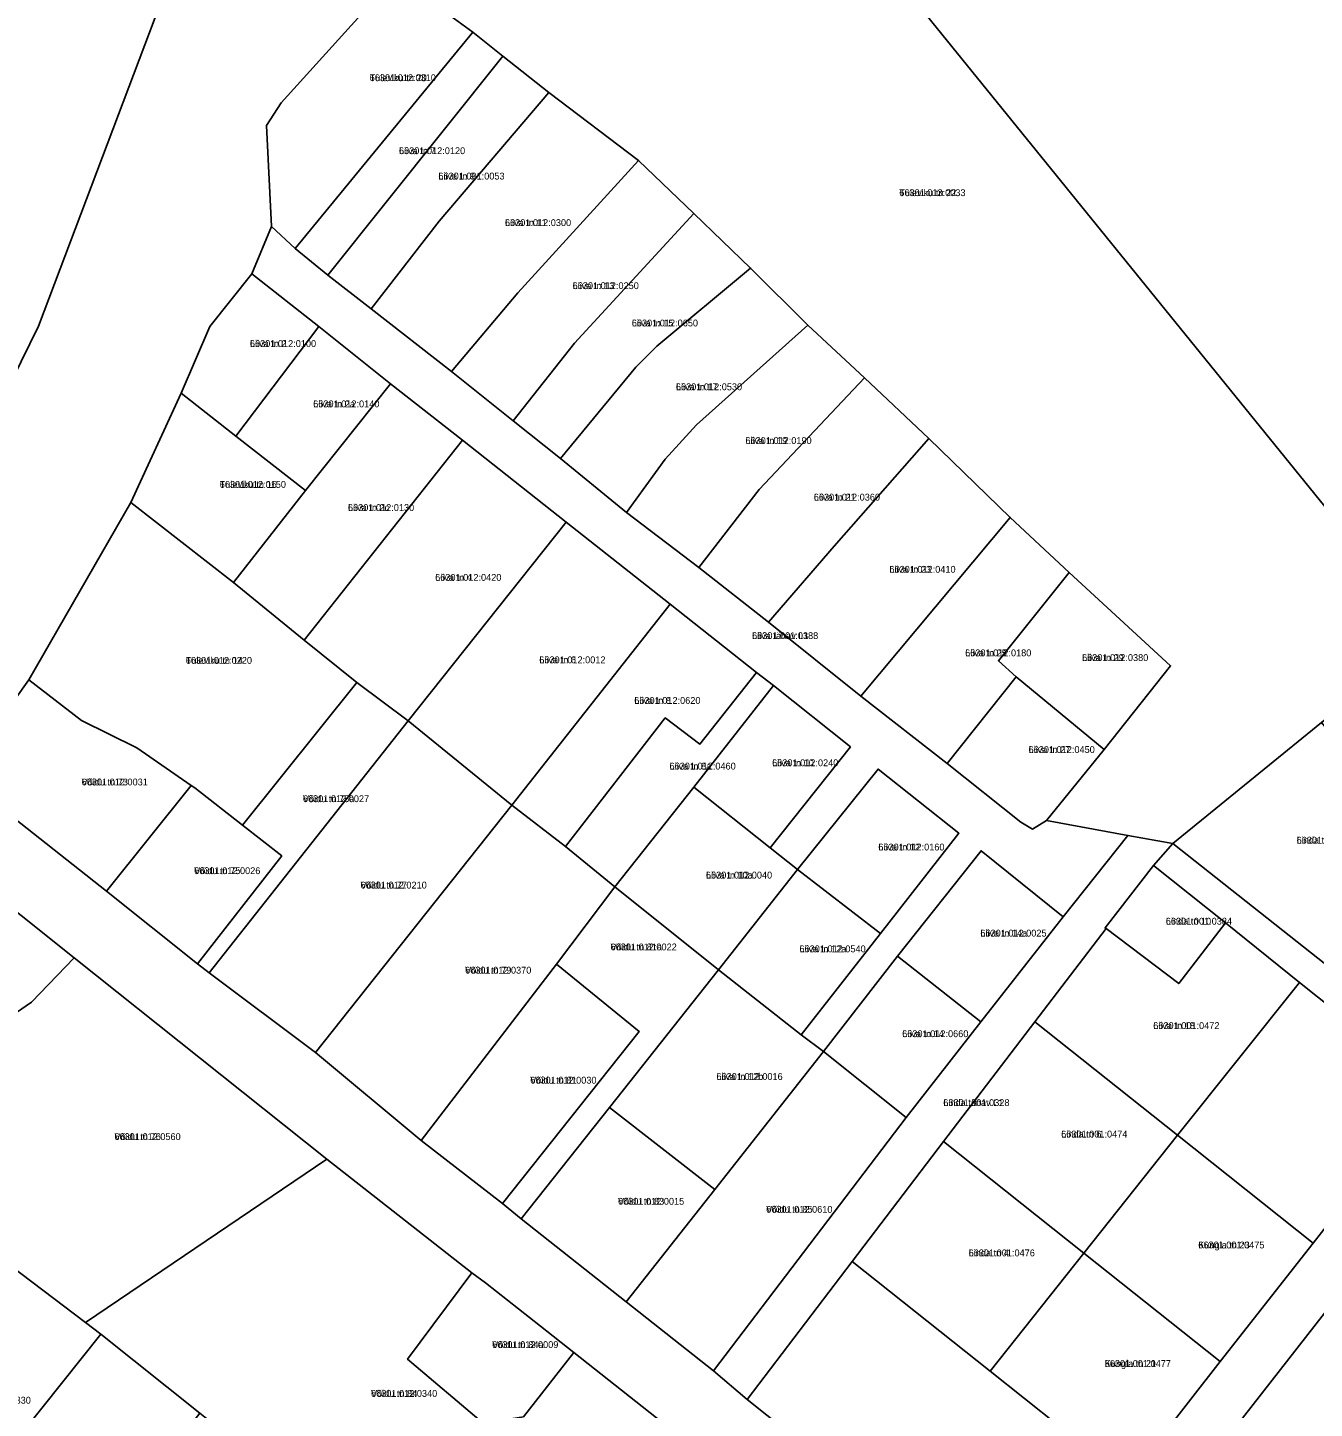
# Model space of a CAD drawing. Extents: x 632278 to 636344, y 6578401 to 6583362.
# Drawn here: x 634837.7 to 635119.5, y 6580958 to 6581260.6 of the extents above; entities that cross this region are included whole.
import ezdxf

# ---------------------------------------------------------------- set-up
doc = ezdxf.new("R2010")
doc.units = 0
for name, color, linetype in [('L_AADRESS', 7, 'Continuous'), ('PIIR', 7, 'Continuous'), ('TUNNUS', 7, 'Continuous')]:
    doc.layers.add(name, color=color, linetype=linetype)

msp = doc.modelspace()

# ---------------------------------------------------------------- linework, layer by layer
at = {"layer": 'PIIR'}
for points in [[(634912.6, 6581276.11), (634946.53, 6581362.44), (634969.39, 6581343.75), (635144.63, 6581127.44), (635121.09, 6581108.27), (635088.56, 6581081.79), (635078.7, 6581083.55), (635060.83, 6581086.86), (635073.49, 6581102.38), (635088.03, 6581120.73), (635065.85, 6581141.16), (635052.91, 6581153.23), (635035.09, 6581170.5), (635020.97, 6581183.85), (635008.56, 6581195.34), (634996.04, 6581207.85), (634983.63, 6581219.79), (634971.52, 6581231.46), (634951.87, 6581246.32), (634941.81, 6581254.33), (634935.24, 6581259.55), (634918.34, 6581271.91)], [(634891.17, 6581216.96), (634890.04, 6581239.13), (634893.28, 6581244.04), (634918.34, 6581271.91), (634935.24, 6581259.55), (634896.29, 6581212.18)], [(634941.81, 6581254.33), (634903.49, 6581206.31), (634896.29, 6581212.18), (634935.24, 6581259.55)], [(634913, 6581198.95), (634903.49, 6581206.31), (634941.81, 6581254.33), (634951.87, 6581246.32), (634927.84, 6581218.12)], [(634913, 6581198.95), (634927.84, 6581218.12), (634951.87, 6581246.32), (634971.52, 6581231.46), (634945.1, 6581202.46), (634930.53, 6581185.23)], [(634930.53, 6581185.23), (634945.1, 6581202.46), (634971.52, 6581231.46), (634983.63, 6581219.79), (634957.47, 6581191.41), (634944.03, 6581174.38)], [(634954.42, 6581166.12), (634944.03, 6581174.38), (634957.47, 6581191.41), (634983.63, 6581219.79), (634996.04, 6581207.85), (634975.49, 6581190.74), (634970.9, 6581186.18)], [(634891.17, 6581216.96), (634896.29, 6581212.18), (634903.49, 6581206.31), (634913, 6581198.95), (634930.53, 6581185.23), (634944.03, 6581174.38), (634954.42, 6581166.12), (634968.89, 6581154.34), (634984.7, 6581142.28), (634999.99, 6581130.26), (635020.23, 6581114.1), (635039.14, 6581099.3), (635055.25, 6581086.43), (635057.76, 6581084.93), (635060.83, 6581086.86), (635078.7, 6581083.55), (635064.51, 6581065.71), (635046.54, 6581080.19), (635028.23, 6581057.07), (635011.99, 6581036.2), (635007.12, 6581039.87), (635024.49, 6581062.1), (635041.69, 6581084.03), (635023.98, 6581098.09), (635006.34, 6581076.09), (635000.36, 6581080.85), (635017.9, 6581102.94), (635001.07, 6581116.44), (634997.38, 6581119.29), (634978.46, 6581134.22), (634955.69, 6581152.16), (634932.94, 6581170.18), (634917.19, 6581182.5), (634901.48, 6581195.03), (634886.85, 6581206.58)], [(634901.48, 6581195.03), (634883.34, 6581171.06), (634871.35, 6581180.44), (634877.61, 6581195.05), (634886.85, 6581206.58)], [(634968.89, 6581154.34), (634954.42, 6581166.12), (634970.9, 6581186.18), (634975.49, 6581190.74), (634996.04, 6581207.85), (635008.56, 6581195.34), (634984.22, 6581173.52), (634977.38, 6581166.03)], [(634883.34, 6581171.06), (634901.48, 6581195.03), (634917.19, 6581182.5), (634898.55, 6581159.15)], [(634968.89, 6581154.34), (634977.38, 6581166.03), (634984.22, 6581173.52), (635008.56, 6581195.34), (635020.97, 6581183.85), (634997.91, 6581159.38), (634984.7, 6581142.28)], [(634898.28, 6581126.31), (634882.81, 6581138.99), (634898.55, 6581159.15), (634917.19, 6581182.5), (634932.94, 6581170.18)], [(634984.7, 6581142.28), (634997.91, 6581159.38), (635020.97, 6581183.85), (635035.09, 6581170.5), (635014.36, 6581146.92), (634999.99, 6581130.26)], [(634871.35, 6581180.44), (634883.34, 6581171.06), (634898.55, 6581159.15), (634882.81, 6581138.99), (634860.3, 6581156.51)], [(634909.84, 6581117.05), (634898.28, 6581126.31), (634932.94, 6581170.18), (634955.69, 6581152.16), (634921.1, 6581108.63)], [(634999.99, 6581130.26), (635014.36, 6581146.92), (635035.09, 6581170.5), (635052.91, 6581153.23), (635020.23, 6581114.1)], [(634860.3, 6581156.51), (634882.81, 6581138.99), (634898.28, 6581126.31), (634909.84, 6581117.05), (634884.81, 6581085.8), (634874.38, 6581094.02), (634873.56, 6581094.5), (634861.66, 6581102.77), (634849.52, 6581108.77), (634838.01, 6581117.66)], [(634921.1, 6581108.63), (634955.69, 6581152.16), (634978.46, 6581134.22), (634943.78, 6581090.22)], [(635020.23, 6581114.1), (635052.91, 6581153.23), (635065.85, 6581141.16), (635050.33, 6581121.83), (635054.24, 6581118.31), (635039.14, 6581099.3)], [(635050.33, 6581121.83), (635065.85, 6581141.16), (635088.03, 6581120.73), (635073.49, 6581102.38), (635054.24, 6581118.31)], [(634955.53, 6581081.13), (634943.78, 6581090.22), (634978.46, 6581134.22), (634997.38, 6581119.29), (634984.95, 6581103.56), (634977.36, 6581109.29)], [(634955.53, 6581081.13), (634977.36, 6581109.29), (634984.95, 6581103.56), (634997.38, 6581119.29), (635001.07, 6581116.44), (634983.65, 6581094.15), (634966.3, 6581072.26)], [(634838.01, 6581117.66), (634849.52, 6581108.77), (634861.66, 6581102.77), (634873.56, 6581094.5), (634855, 6581071.36), (634822.93, 6581096.59)], [(634909.84, 6581117.05), (634921.1, 6581108.63), (634877.49, 6581053.44), (634874.93, 6581055.45), (634893.4, 6581079.06), (634884.81, 6581085.8)], [(634983.65, 6581094.15), (635001.07, 6581116.44), (635017.9, 6581102.94), (635000.36, 6581080.85)], [(635039.14, 6581099.3), (635054.24, 6581118.31), (635073.49, 6581102.38), (635060.83, 6581086.86), (635057.76, 6581084.93), (635055.25, 6581086.43)], [(634877.49, 6581053.44), (634921.1, 6581108.63), (634943.78, 6581090.22), (634900.78, 6581036.03)], [(635088.56, 6581081.79), (635121.09, 6581108.27), (635147.43, 6581075.93), (635122.03, 6581055.25)], [(635023.98, 6581098.09), (635041.69, 6581084.03), (635024.49, 6581062.1), (635006.34, 6581076.09)], [(634873.56, 6581094.5), (634874.38, 6581094.02), (634884.81, 6581085.8), (634893.4, 6581079.06), (634874.93, 6581055.45), (634855, 6581071.36)], [(634989.03, 6581054.08), (634966.3, 6581072.26), (634983.65, 6581094.15), (635000.36, 6581080.85), (635006.34, 6581076.09)], [(634900.78, 6581036.03), (634943.78, 6581090.22), (634955.53, 6581081.13), (634966.3, 6581072.26), (634953.54, 6581055.33), (634923.95, 6581016.73)], [(634797.56, 6581064.7), (634813.01, 6581084.53), (634847.95, 6581056.76), (634838.59, 6581047), (634823.5, 6581036.63), (634816.61, 6581047.12)], [(635018.27, 6580990.22), (634995.29, 6580959.95), (634987.94, 6580966.28), (635030.15, 6581021.74), (635046.51, 6581042.71), (635064.51, 6581065.71), (635078.7, 6581083.55), (635088.56, 6581081.79), (635084.3, 6581076.94), (635073.69, 6581063.3), (635073.91, 6581063.14), (635058.32, 6581042.73), (635038.31, 6581016.48)], [(635046.54, 6581080.19), (635064.51, 6581065.71), (635046.51, 6581042.71), (635028.23, 6581057.07)], [(635084.3, 6581076.94), (635088.56, 6581081.79), (635122.03, 6581055.25), (635156.7, 6581027.77), (635150.67, 6581023.97), (635116.28, 6581051.35), (635100.04, 6581064.4)], [(634989.03, 6581054.08), (635006.34, 6581076.09), (635024.49, 6581062.1), (635007.12, 6581039.87)], [(635073.69, 6581063.3), (635084.3, 6581076.94), (635100.04, 6581064.4), (635089.81, 6581051.08), (635073.91, 6581063.14)], [(634966.3, 6581072.26), (634989.03, 6581054.08), (634965.17, 6581023.94), (634945.82, 6580999.55), (634941.76, 6581002.89), (634971.67, 6581040.58), (634953.54, 6581055.32)], [(635058.32, 6581042.73), (635073.91, 6581063.14), (635089.81, 6581051.08), (635100.04, 6581064.4), (635116.28, 6581051.35), (635089.57, 6581017.88)], [(634831.74, 6580991), (634809.41, 6581009.48), (634816.8, 6581018.45), (634823.5, 6581036.63), (634838.59, 6581047), (634847.95, 6581056.76), (634903.28, 6581012.64), (634850.41, 6580976.85)], [(634971.67, 6581040.58), (634941.76, 6581002.89), (634923.95, 6581016.73), (634953.54, 6581055.33)], [(635028.23, 6581057.07), (635046.51, 6581042.71), (635030.15, 6581021.74), (635011.99, 6581036.2)], [(635055.23, 6580912.22), (635078.63, 6580942.2), (635098.91, 6580968.26), (635119.24, 6580994.25), (635124.71, 6581001.23), (635141.35, 6581018.03), (635150.67, 6581023.97), (635156.7, 6581027.77), (635176.39, 6581040.35), (635202.1, 6581056.83), (635209.39, 6581047.9), (635185.68, 6581032.75), (635160.13, 6581016.49), (635148.57, 6581009.1), (635133.75, 6580994.18), (635127.71, 6580986.57), (635064.19, 6580905.18)], [(634989.03, 6581054.08), (635007.12, 6581039.87), (635011.99, 6581036.2), (634988.21, 6581005.98), (634965.17, 6581023.94)], [(635089.57, 6581017.88), (635116.28, 6581051.35), (635150.67, 6581023.97), (635141.35, 6581018.03), (635124.71, 6581001.23), (635119.24, 6580994.25)], [(635038.31, 6581016.48), (635058.32, 6581042.73), (635089.57, 6581017.88), (635069.02, 6580992)], [(634968.82, 6580981.35), (634988.21, 6581005.98), (635011.99, 6581036.2), (635030.15, 6581021.74), (634987.94, 6580966.28)], [(634965.17, 6581023.94), (634988.21, 6581005.98), (634968.82, 6580981.35), (634945.82, 6580999.55)], [(635018.27, 6580990.22), (635038.31, 6581016.48), (635069.02, 6580992), (635048.49, 6580966.2)], [(635069.02, 6580992), (635089.57, 6581017.88), (635119.24, 6580994.25), (635098.91, 6580968.26)], [(634875.44, 6580957), (634853.77, 6580974.29), (634850.41, 6580976.85), (634903.28, 6581012.64), (634934.98, 6580987.7), (634920.94, 6580968.79), (634937.47, 6580954.77), (634946.29, 6580956.14), (634957.35, 6580970.29), (634975.46, 6580955.95), (634950.81, 6580940.29), (634911.03, 6580914.84), (634907.81, 6580920.62), (634897.33, 6580939.45)], [(635048.49, 6580966.2), (635069.02, 6580992), (635098.91, 6580968.26), (635078.63, 6580942.2)], [(634831.74, 6580991), (634850.41, 6580976.85), (634853.77, 6580974.29), (634815.84, 6580926.73), (634794.1, 6580943.95)], [(634995.29, 6580959.95), (635018.27, 6580990.22), (635048.49, 6580966.2), (635078.63, 6580942.2), (635055.23, 6580912.22)], [(634934.98, 6580987.7), (634937.98, 6580985.51), (634950.06, 6580976.06), (634957.35, 6580970.29), (634946.29, 6580956.14), (634937.47, 6580954.77), (634920.94, 6580968.79)], [(635127.71, 6580986.57), (635212.9, 6580920.1), (635148.77, 6580837.91), (635064.19, 6580905.18)], [(634815.84, 6580926.73), (634853.77, 6580974.29), (634875.44, 6580957), (634862.3, 6580940.1), (634850.08, 6580924.68), (634837.9, 6580909.32)]]:
    msp.add_lwpolyline(points, close=True, dxfattribs=at)
for points in [[(634918.34, 6581271.91), (634893.28, 6581244.04), (634890.04, 6581239.13), (634891.17, 6581216.96), (634886.85, 6581206.58), (634877.61, 6581195.05), (634871.35, 6581180.44), (634860.3, 6581156.51), (634838.01, 6581117.66), (634822.93, 6581096.59), (634813.01, 6581084.53), (634783.31, 6581109.93), (634796.07, 6581117.73), (634809.38, 6581135.31), (634822.93, 6581160.31), (634840.08, 6581195.15), (634865.69, 6581262.77)], [(634865.69, 6581262.77), (634840.08, 6581195.15), (634822.93, 6581160.31), (634809.38, 6581135.31), (634796.07, 6581117.73), (634764.96, 6581143.81), (634714.31, 6581221.64), (634742.28, 6581238.5), (634753.1, 6581245.04), (634757.02, 6581255.3), (634760.32, 6581263.95)], [(634822.93, 6581096.59), (634855, 6581071.36), (634874.93, 6581055.45), (634877.49, 6581053.44), (634900.78, 6581036.03), (634923.95, 6581016.73), (634941.76, 6581002.89), (634945.82, 6580999.55), (634968.82, 6580981.35), (634987.94, 6580966.28), (634995.29, 6580959.95), (635055.23, 6580912.22), (635064.19, 6580905.18), (635148.77, 6580837.91), (635156.38, 6580831.87), (635270.51, 6580741.99)], [(635262.41, 6580731.79), (635191.38, 6580787.53), (635172.4, 6580802.21), (635167.86, 6580805.69), (635151.82, 6580817.9), (635132.3, 6580833.01), (635112.35, 6580848.22), (635094.77, 6580862.04), (635091.62, 6580864.51), (635054.05, 6580893.93), (635045.98, 6580900.27), (635022.45, 6580918.7), (634997.82, 6580937.94), (634977.82, 6580954.21), (634975.46, 6580955.95), (634957.35, 6580970.29), (634950.06, 6580976.06), (634937.98, 6580985.51), (634934.98, 6580987.7), (634903.28, 6581012.64), (634847.95, 6581056.76), (634813.01, 6581084.53)]]:
    msp.add_lwpolyline(points, dxfattribs=at)

# ---------------------------------------------------------------- texts
at = {"layer": 'L_AADRESS'}
for s, p in [('Tuleviku tn 20', (634912.64, 6581248.82)), ('Liiva tn 7', (634919.05, 6581232.83)), ('Liiva tn 9', (634927.68, 6581227.27)), ('Tuleviku tn 22', (635028.62, 6581223.63)), ('Liiva tn 11', (634942.26, 6581217.07)), ('Liiva tn 13', (634957.08, 6581203.26)), ('Liiva tn 15', (634970.04, 6581195.08)), ('Liiva tn 2', (634886.41, 6581190.58)), ('Liiva tn 17', (634979.7, 6581181.1)), ('Liiva tn 2a', (634900.27, 6581177.36)), ('Liiva tn 19', (634994.93, 6581169.32)), ('Tuleviku tn 16', (634879.8, 6581159.71)), ('Liiva tn 21', (635009.9, 6581156.92)), ('Liiva tn 2c', (634907.88, 6581154.64)), ('Liiva tn 23', (635026.45, 6581141.11)), ('Liiva tn 4', (634926.98, 6581139.34)), ('Liiva tänav L1', (634996.37, 6581126.58)), ('Tuleviku tn 14', (634872.37, 6581121.16)), ('Liiva tn 6', (634949.78, 6581121.28)), ('Liiva tn 25', (635043.04, 6581122.81)), ('Liiva tn 29', (635068.65, 6581121.77)), ('Liiva tn 8', (634970.58, 6581112.38)), ('Liiva tn 10', (635000.77, 6581098.72)), ('Liiva tn 27', (635056.93, 6581101.62)), ('Liiva tn 8a', (634978.3, 6581097.99)), ('Võidu tn 73', (634849.56, 6581094.51)), ('Võidu tn 75a', (634898.02, 6581090.85)), ('Linda tn 12', (635115.64, 6581081.76)), ('Liiva tn 12', (635024.02, 6581080.26)), ('Võidu tn 75', (634874.2, 6581075.08)), ('Võidu tn 77', (634910.64, 6581071.92)), ('Liiva tn 10a', (634986.28, 6581074.11)), ('Linda tn 10', (635086.99, 6581064.01)), ('Liiva tn 14a', (635046.37, 6581061.4)), ('Võidu tn 81a', (634965.39, 6581058.37)), ('Liiva tn 12a', (635006.76, 6581057.96)), ('Võidu tn 79', (634933.54, 6581053.28)), ('Liiva tn 14', (635029.25, 6581039.36)), ('Liiva tn 18', (635084.23, 6581041.14)), ('Võidu tn 81', (634947.81, 6581029.18)), ('Liiva tn 12b', (634988.58, 6581029.98)), ('Linda tänav L1', (635038.25, 6581024.26)), ('Linda tn 6', (635064.07, 6581017.37)), ('Võidu tn 76', (634856.75, 6581016.81)), ('Võidu tn 83', (634967.02, 6581002.64)), ('Võidu tn 85', (634999.48, 6581000.88)), ('Kungla tn 23', (635094.09, 6580993.07)), ('Linda tn 4', (635043.81, 6580991.34)), ('Võidu tn 84a', (634939.46, 6580971.24)), ('Kungla tn 21', (635073.61, 6580967.1)), ('Võidu tn 84', (634912.93, 6580960.55))]:
    msp.add_text(s, height=1.5, dxfattribs=at).set_placement(p)
at = {"layer": 'TUNNUS'}
for s, p in [('66301:012:0310', (634912.64, 6581248.82)), ('66301:012:0120', (634919.05, 6581232.83)), ('66301:001:0053', (634927.68, 6581227.27)), ('66301:013:0033', (635028.62, 6581223.63)), ('66301:012:0300', (634942.26, 6581217.07)), ('66301:012:0250', (634957.08, 6581203.26)), ('66301:012:0650', (634970.04, 6581195.08)), ('66301:012:0100', (634886.41, 6581190.58)), ('66301:012:0530', (634979.7, 6581181.1)), ('66301:012:0140', (634900.27, 6581177.36)), ('66301:012:0190', (634994.93, 6581169.32)), ('66301:012:0150', (634879.8, 6581159.71)), ('66301:012:0360', (635009.9, 6581156.92)), ('66301:012:0130', (634907.88, 6581154.64)), ('66301:012:0410', (635026.45, 6581141.11)), ('66301:012:0420', (634926.98, 6581139.34)), ('66301:001:0388', (634996.37, 6581126.58)), ('66301:012:0220', (634872.37, 6581121.16)), ('66301:012:0012', (634949.78, 6581121.28)), ('66301:012:0180', (635043.04, 6581122.81)), ('66301:012:0380', (635068.65, 6581121.77)), ('66301:012:0620', (634970.58, 6581112.38)), ('66301:012:0240', (635000.77, 6581098.72)), ('66301:012:0450', (635056.93, 6581101.62)), ('66301:012:0460', (634978.3, 6581097.99)), ('66301:012:0031', (634849.56, 6581094.51)), ('66301:012:0027', (634898.02, 6581090.85)), ('66301:012:0019', (635115.64, 6581081.76)), ('66301:012:0160', (635024.02, 6581080.26)), ('66301:012:0026', (634874.2, 6581075.08)), ('66301:012:0210', (634910.64, 6581071.92)), ('66301:012:0040', (634986.28, 6581074.11)), ('66301:001:0384', (635086.99, 6581064.01)), ('66301:012:0025', (635046.37, 6581061.4)), ('66301:012:0022', (634965.39, 6581058.37)), ('66301:012:0540', (635006.76, 6581057.96)), ('66301:012:0370', (634933.54, 6581053.28)), ('66301:012:0660', (635029.25, 6581039.36)), ('66301:001:0472', (635084.23, 6581041.14)), ('66301:012:0030', (634947.81, 6581029.18)), ('66301:012:0016', (634988.58, 6581029.98)), ('66301:001:0328', (635038.25, 6581024.26)), ('66301:001:0474', (635064.07, 6581017.37)), ('66301:012:0560', (634856.75, 6581016.81)), ('66301:012:0015', (634967.02, 6581002.64)), ('66301:012:0610', (634999.48, 6581000.88)), ('66301:001:0475', (635094.09, 6580993.07)), ('66301:001:0476', (635043.81, 6580991.34)), ('66301:012:0009', (634939.46, 6580971.24)), ('66301:001:0477', (635073.61, 6580967.1)), ('66301:012:0340', (634912.93, 6580960.55)), ('66301:012:0330', (634823.94, 6580959.06))]:
    msp.add_text(s, height=1.5, dxfattribs=at).set_placement(p)

doc.saveas('drawing.dxf')
